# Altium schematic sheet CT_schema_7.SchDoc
size 287 x 160 mm
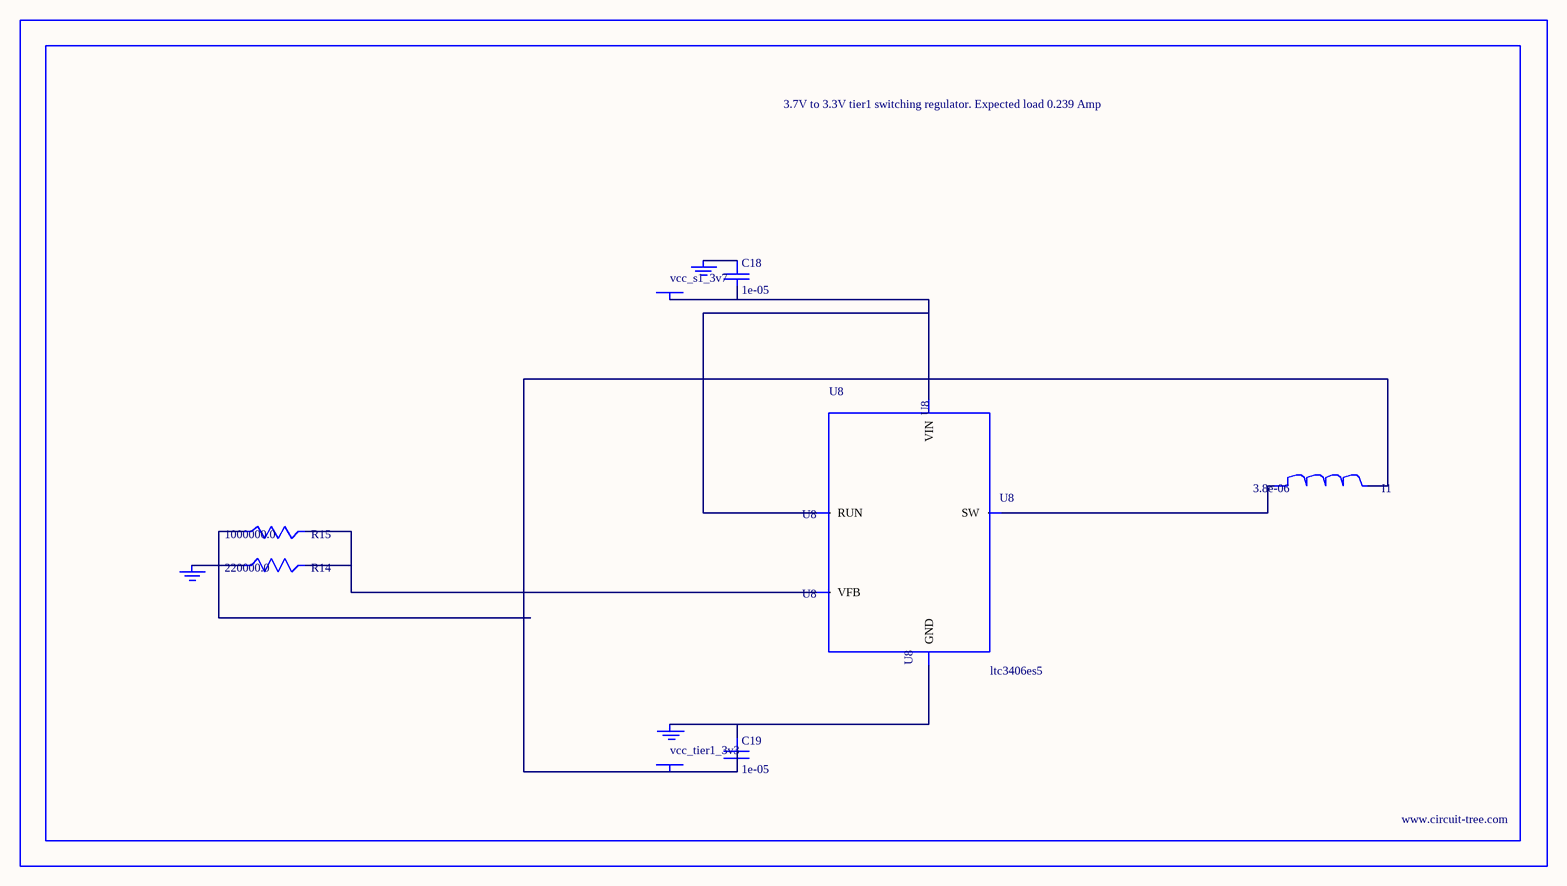
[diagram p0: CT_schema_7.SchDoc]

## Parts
BORDER6  (no value)
C18  1e-05  [C0805]
C19  1e-05  [C0805]
GND_INSTANCE_6_0  (no value)
GND_INSTANCE_6_1  (no value)
GND_INSTANCE_6_2  (no value)
I1  3.8e-06  [DR1040]
POWER_INSTANCE_6_0  vcc_tier1_3v3
POWER_INSTANCE_6_1  vcc_s1_3v7
R14  220000.0  [R0603]
R15  1000000.0  [R0603]
U8  ltc3406es5  [TSOT-23-5]

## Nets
NetC18_1: C18.1 GND_INSTANCE_6_1.0(GND)
NetC18_2: C18.2 POWER_INSTANCE_6_1.0(PWR) U8.1(RUN) U8.4(VIN)
NetC19_1: C19.1 GND_INSTANCE_6_0.0(GND) U8.2(GND)
NetC19_2: C19.2 I1.2 POWER_INSTANCE_6_0.0(PWR) R15.1
NetGND_INSTANCE_6_2_0: GND_INSTANCE_6_2.0(GND) R14.1
NetI1_1: I1.1 U8.3(SW)
NetR14_2: R14.2 R15.2 U8.5(VFB)

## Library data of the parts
BORDER6 = BORDER_PAGE6
C18 C19 = C0805C106K8RACTU
GND_INSTANCE_6_0-GND_INSTANCE_6_2 = GND
I1 = DR1040-3R8-R
POWER_INSTANCE_6_0 POWER_INSTANCE_6_1 = PWR
R14 = RC0603JR-07220KL
R15 = RC0603JR-071ML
